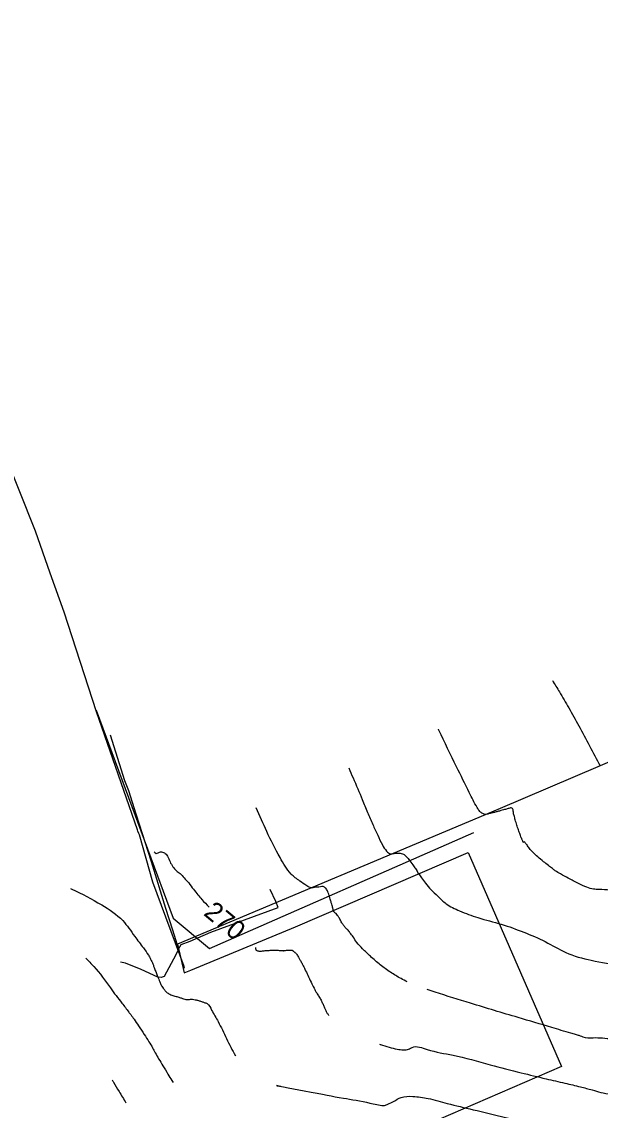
# Model space of a CAD drawing. Extents: x -478645 to -472650, y -1118147 to -1113892.
# Drawn here: x -475798.3 to -475676.6, y -1117014.2 to -1116785 of the extents above; entities that cross this region are included whole.
import ezdxf

# ---------------------------------------------------------------- set-up
doc = ezdxf.new("R2010")
doc.units = 0
for name, color, linetype in [('ObPÚ', 7, 'Continuous'), ('telekomunikační kabel_O2', 7, 'Continuous'), ('VAK_vodovod', 7, 'Continuous'), ('Vrstevnice_hlavni', 7, 'Continuous'), ('Vrstevnice_popis', 7, 'Continuous'), ('Vrstevnice_vedlejsi', 7, 'Continuous')]:
    doc.layers.add(name, color=color, linetype=linetype)

msp = doc.modelspace()

# ---------------------------------------------------------------- linework, layer by layer
at = {"layer": 'ObPÚ'}
msp.add_lwpolyline([(-475428.97, -1116843.96), (-475493.62, -1116794.93), (-475510.01, -1116785), (-475504.39, -1116792.65), (-475500.17, -1116802.88), (-475548.74, -1116836.09), (-475563.15, -1116845.95), (-475582.38, -1116858.98), (-475609.93, -1116877.62), (-475644, -1116900.2), (-475634.09, -1116923.52), (-475698.19, -1116950.87), (-475765.52, -1116979.2), (-475764.15, -1116985.27), (-475762.77, -1116984.68), (-475740.75, -1116975.6), (-475704.37, -1116959.91), (-475684.75, -1117004.96), (-475721.12, -1117020.7)], dxfattribs=at)
at = {"layer": 'telekomunikační kabel_O2'}
for points in [[(-475779.72, -1116935.16), (-475776.72, -1116944.8), (-475775.82, -1116946.89)], [(-475775.82, -1116946.89), (-475774.3, -1116951.81), (-475771.12, -1116961.84), (-475768.06, -1116971.62), (-475766.62, -1116976.22), (-475765.34, -1116980.29)], [(-475765.34, -1116980.29), (-475764.8, -1116979.28), (-475762.86, -1116978.62), (-475758.55, -1116976.73), (-475744.37, -1116971.54), (-475744.83, -1116970.26), (-475746.06, -1116967.73)], [(-475765.34, -1116980.29), (-475765.92, -1116981.46), (-475768.35, -1116986.07), (-475768.98, -1116986.28), (-475769.68, -1116986.19), (-475773.18, -1116984.59), (-475776.5, -1116983.23), (-475777.53, -1116983.05)]]:
    msp.add_lwpolyline(points, dxfattribs=at)
at = {"layer": 'VAK_vodovod'}
for points in [[(-475764.07, -1116984.29), (-475764.159, -1116983.95), (-475770.76, -1116966.2), (-475773.519, -1116956.18), (-475773.699, -1116955.909), (-475773.909, -1116955.44), (-475773.98, -1116955.18), (-475782.599, -1116930.34), (-475789.389, -1116909.29), (-475792.36, -1116901.129), (-475795.449, -1116892.25), (-475795.679, -1116891.569), (-475801.449, -1116877.079), (-475803.873, -1116870.356), (-475810.739, -1116851.899), (-475813.889, -1116838.01), (-475814.349, -1116835.61), (-475816.44, -1116816.799), (-475816.731, -1116810.878)], [(-475782.684, -1116929.977), (-475766.44, -1116973.781), (-475758.82, -1116980.133), (-475703.189, -1116955.74)]]:
    msp.add_lwpolyline(points, dxfattribs=at)
at = {"layer": 'Vrstevnice_hlavni'}
for points in [[(-475770.444, -1116959.812), (-475770.027, -1116960.112), (-475769.102, -1116959.807), (-475768.308, -1116960.004), (-475767.648, -1116960.702), (-475767.119, -1116961.902), (-475766.503, -1116962.916), (-475765.799, -1116963.743), (-475765.007, -1116964.385), (-475764.139, -1116965.254), (-475763.195, -1116966.349), (-475762.174, -1116967.671), (-475761.246, -1116968.823), (-475760.408, -1116969.806), (-475758.917, -1116971.433)], [(-475752.155, -1116974.761), (-475752.278, -1116974.524), (-475752.331, -1116974.447), (-475752.377, -1116974.41), (-475752.415, -1116974.415), (-475752.45, -1116974.42), (-475752.482, -1116974.426), (-475752.541, -1116974.439)], [(-475749.112, -1116979.911), (-475749.084, -1116980.363), (-475748.966, -1116980.529), (-475748.744, -1116980.634), (-475748.419, -1116980.68), (-475748.159, -1116980.701), (-475747.966, -1116980.699), (-475747.84, -1116980.673), (-475747.554, -1116980.64), (-475747.109, -1116980.599), (-475746.506, -1116980.551), (-475746.066, -1116980.515), (-475745.792, -1116980.49), (-475745.682, -1116980.477), (-475745.442, -1116980.476), (-475745.072, -1116980.485), (-475744.572, -1116980.507), (-475744.144, -1116980.533), (-475743.788, -1116980.563), (-475743.504, -1116980.598), (-475743.314, -1116980.614), (-475743.221, -1116980.611), (-475743.223, -1116980.59), (-475743.216, -1116980.574), (-475743.201, -1116980.564), (-475743.178, -1116980.559), (-475742.98, -1116980.549), (-475742.607, -1116980.532), (-475742.059, -1116980.51), (-475741.674, -1116980.502), (-475741.452, -1116980.509), (-475741.392, -1116980.531), (-475741.34, -1116980.559), (-475741.298, -1116980.593), (-475741.264, -1116980.634), (-475741.175, -1116980.708), (-475741.032, -1116980.815), (-475740.833, -1116980.954), (-475740.632, -1116981.157), (-475740.429, -1116981.424), (-475740.222, -1116981.754), (-475739.954, -1116982.217), (-475739.622, -1116982.813), (-475739.228, -1116983.543), (-475738.734, -1116984.524), (-475738.14, -1116985.756), (-475737.446, -1116987.241), (-475736.821, -1116988.49), (-475736.265, -1116989.503), (-475735.779, -1116990.281), (-475735.354, -1116991.032), (-475734.993, -1116991.754), (-475734.695, -1116992.449), (-475734.397, -1116993.087), (-475734.1, -1116993.67), (-475733.804, -1116994.197), (-475733.754, -1116994.287)], [(-475723.019, -1117000.326), (-475722.854, -1117000.379), (-475721.016, -1117000.925), (-475719.348, -1117001.335), (-475717.982, -1117001.478), (-475716.917, -1117001.356), (-475716.153, -1117000.967), (-475713.042, -1117001.384), (-475707.582, -1117002.608), (-475699.774, -1117004.638), (-475693.246, -1117006.296), (-475687.998, -1117007.584), (-475684.03, -1117008.499), (-475680.792, -1117009.282), (-475678.284, -1117009.933), (-475676.506, -1117010.452), (-475672.106, -1117010.892), (-475665.083, -1117011.253)]]:
    msp.add_spline(points, degree=3, dxfattribs=at)
at = {"layer": 'Vrstevnice_vedlejsi'}
for points in [[(-475686.67, -1116923.726), (-475685.202, -1116926.107), (-475683.236, -1116929.464), (-475681.126, -1116933.254), (-475676.619, -1116941.699)], [(-475589.216, -1117124.456), (-475591.425, -1117122.152), (-475592.659, -1117119.687), (-475592.919, -1117117.061), (-475592.203, -1117114.274), (-475589.888, -1117108.69), (-475585.974, -1117100.309), (-475580.459, -1117089.13), (-475576.812, -1117078.878), (-475575.031, -1117069.554), (-475575.117, -1117061.157), (-475574.636, -1117054.237), (-475573.59, -1117048.792), (-475571.977, -1117044.824), (-475570.898, -1117041.096), (-475570.353, -1117037.61), (-475570.342, -1117034.364), (-475569.433, -1117028.448), (-475567.626, -1117019.86), (-475564.922, -1117008.6), (-475567.235, -1116998.791), (-475574.567, -1116990.433), (-475586.916, -1116983.524), (-475597.186, -1116978.942), (-475605.377, -1116976.688), (-475611.489, -1116976.76), (-475618.025, -1116976.271), (-475624.984, -1116975.222), (-475632.368, -1116973.612), (-475641.296, -1116972.066), (-475651.771, -1116970.583), (-475663.792, -1116969.164), (-475672.17, -1116968.202), (-475676.905, -1116967.697), (-475677.998, -1116967.647), (-475679.435, -1116967.24), (-475681.215, -1116966.473), (-475683.339, -1116965.348), (-475684.96, -1116964.449), (-475686.077, -1116963.776), (-475686.69, -1116963.33), (-475687.51, -1116962.691), (-475688.536, -1116961.862), (-475689.768, -1116960.841), (-475690.758, -1116959.916), (-475691.505, -1116959.085), (-475692.008, -1116958.349), (-475692.376, -1116957.889), (-475692.608, -1116957.705), (-475692.704, -1116957.796), (-475692.881, -1116957.567), (-475693.138, -1116957.016), (-475693.475, -1116956.145), (-475693.813, -1116955.193), (-475694.151, -1116954.161), (-475694.489, -1116953.05), (-475694.736, -1116952.145), (-475694.892, -1116951.446), (-475694.956, -1116950.954), (-475695.105, -1116950.65), (-475695.339, -1116950.535), (-475695.658, -1116950.608), (-475696, -1116950.692), (-475696.364, -1116950.788), (-475696.75, -1116950.896), (-475697.237, -1116951.031), (-475697.824, -1116951.194), (-475698.511, -1116951.385), (-475699.213, -1116951.569), (-475699.928, -1116951.744), (-475700.656, -1116951.912), (-475701.333, -1116951.752), (-475701.956, -1116951.263), (-475702.527, -1116950.446), (-475704.154, -1116947.323), (-475706.837, -1116941.893), (-475710.575, -1116934.156), (-475710.663, -1116933.973)], [(-475729.527, -1116942.126), (-475728.611, -1116944.232), (-475726.669, -1116948.766), (-475725.544, -1116951.506), (-475724.466, -1116954.013), (-475723.434, -1116956.285), (-475722.449, -1116958.323), (-475721.548, -1116959.642), (-475720.729, -1116960.242), (-475719.994, -1116960.123), (-475719.328, -1116960.075), (-475718.731, -1116960.097), (-475718.204, -1116960.189), (-475717.583, -1116960.628), (-475716.868, -1116961.415), (-475716.061, -1116962.548), (-475715.508, -1116963.328), (-475715.21, -1116963.755), (-475715.167, -1116963.828), (-475715.132, -1116963.894), (-475715.104, -1116963.952), (-475715.085, -1116964.003), (-475714.792, -1116964.431), (-475714.224, -1116965.237), (-475713.382, -1116966.419), (-475712.234, -1116967.726), (-475710.782, -1116969.156), (-475709.024, -1116970.711), (-475706.212, -1116972.209), (-475702.344, -1116973.649), (-475697.421, -1116975.031), (-475692.698, -1116976.716), (-475688.176, -1116978.703), (-475683.853, -1116980.992), (-475678.496, -1116982.63), (-475672.102, -1116983.615), (-475664.674, -1116983.949), (-475657.807, -1116984.398), (-475651.502, -1116984.961), (-475645.759, -1116985.639), (-475640.754, -1116986.347), (-475636.487, -1116987.086), (-475632.96, -1116987.855), (-475627.187, -1116988.328), (-475619.17, -1116988.503), (-475608.909, -1116988.382), (-475599.585, -1116989.691), (-475591.198, -1116992.428), (-475583.75, -1116996.595), (-475579.328, -1117001.637), (-475577.932, -1117007.554), (-475579.563, -1117014.345), (-475580.658, -1117021.082), (-475581.217, -1117027.766), (-475581.24, -1117034.395), (-475582.353, -1117041.517), (-475584.557, -1117049.132), (-475587.852, -1117057.238), (-475590.037, -1117063.798), (-475591.112, -1117068.811)], [(-475717.205, -1116987.161), (-475718.526, -1116986.479), (-475720.741, -1116985.146), (-475722.885, -1116983.579), (-475724.958, -1116981.78), (-475726.601, -1116980.203), (-475727.814, -1116978.85), (-475728.597, -1116977.719), (-475729.263, -1116976.822), (-475729.811, -1116976.161), (-475730.242, -1116975.734), (-475730.666, -1116975.194), (-475731.082, -1116974.541), (-475731.491, -1116973.775), (-475731.855, -1116973.196), (-475732.174, -1116972.806), (-475732.448, -1116972.604), (-475732.637, -1116972.443), (-475732.741, -1116972.325), (-475732.761, -1116972.248), (-475732.78, -1116972.148), (-475732.799, -1116972.022), (-475732.818, -1116971.873), (-475732.873, -1116971.625), (-475732.966, -1116971.279), (-475733.095, -1116970.835), (-475733.299, -1116970.169), (-475733.575, -1116969.283), (-475733.925, -1116968.175), (-475734.359, -1116967.454), (-475734.877, -1116967.121), (-475735.478, -1116967.174), (-475736.089, -1116967.235), (-475736.708, -1116967.302), (-475737.336, -1116967.376), (-475738.368, -1116966.928), (-475739.805, -1116965.959), (-475741.646, -1116964.467), (-475743.969, -1116960.984), (-475746.775, -1116955.511), (-475748.963, -1116950.527)], [(-475788.03, -1116967.518), (-475787.795, -1116967.629), (-475781.498, -1116970.952), (-475777.078, -1116974.275), (-475774.537, -1116977.597), (-475772.727, -1116980.026), (-475771.647, -1116981.561), (-475771.297, -1116982.202), (-475770.979, -1116982.851), (-475770.692, -1116983.509), (-475770.437, -1116984.176), (-475770.136, -1116984.956), (-475769.79, -1116985.85), (-475769.398, -1116986.858), (-475769.136, -1116987.532), (-475769.004, -1116987.871), (-475769.002, -1116987.876), (-475769.001, -1116987.879), (-475769, -1116987.882), (-475768.999, -1116987.883), (-475768.999, -1116987.884), (-475768.998, -1116987.885), (-475768.852, -1116988.086), (-475768.561, -1116988.488), (-475768.125, -1116989.09), (-475767.529, -1116989.58), (-475766.772, -1116989.959), (-475765.856, -1116990.227), (-475765.092, -1116990.457), (-475764.483, -1116990.649), (-475764.027, -1116990.804), (-475763.601, -1116990.885), (-475763.205, -1116990.894), (-475762.84, -1116990.829), (-475762.377, -1116990.842), (-475761.816, -1116990.934), (-475761.157, -1116991.103), (-475760.523, -1116991.296), (-475759.914, -1116991.513), (-475759.331, -1116991.753), (-475758.359, -1116993.097), (-475756.997, -1116995.545), (-475755.247, -1116999.097), (-475753.369, -1117002.735)], [(-475784.856, -1116982.194), (-475783.127, -1116983.939), (-475779.673, -1116988.456), (-475777.228, -1116991.651), (-475775.793, -1116993.524), (-475775.368, -1116994.076), (-475774.686, -1116995.045), (-475773.746, -1116996.433), (-475772.548, -1116998.239), (-475771.564, -1116999.784), (-475770.793, -1117001.068), (-475770.234, -1117002.092), (-475769.508, -1117003.352), (-475768.615, -1117004.851), (-475767.555, -1117006.586), (-475766.714, -1117007.974), (-475766.472, -1117008.379)], [(-475648.003, -1117000.173), (-475655.316, -1116999.958), (-475662.118, -1116999.729), (-475668.41, -1116999.485), (-475674.19, -1116999.225), (-475678.133, -1116999.004), (-475680.239, -1116998.823), (-475680.506, -1116998.681), (-475681.023, -1116998.492), (-475681.789, -1116998.255), (-475682.805, -1116997.969), (-475686.83, -1116996.779), (-475693.865, -1116994.683), (-475703.91, -1116991.682), (-475711.368, -1116989.315), (-475712.997, -1116988.771)], [(-475779.319, -1117007.791), (-475779.013, -1117008.308), (-475777.842, -1117010.255), (-475776.381, -1117012.646)], [(-475743.816, -1117009.188), (-475744.435, -1117009.073), (-475738.882, -1117010.109), (-475730.644, -1117011.656), (-475725.08, -1117012.685), (-475722.191, -1117013.195), (-475721.975, -1117013.186), (-475721.285, -1117012.901), (-475720.12, -1117012.341), (-475718.481, -1117011.506), (-475716.047, -1117011.297), (-475712.82, -1117011.716), (-475708.798, -1117012.762), (-475703.378, -1117014.091), (-475696.56, -1117015.703), (-475688.344, -1117017.599), (-475681.639, -1117019.22), (-475676.446, -1117020.568), (-475672.765, -1117021.642), (-475668.29, -1117022.417), (-475663.022, -1117022.893), (-475656.96, -1117023.071), (-475651.811, -1117023.298), (-475647.576, -1117023.576), (-475644.255, -1117023.903), (-475641.565, -1117024.203), (-475639.507, -1117024.475)]]:
    msp.add_spline(points, degree=3, dxfattribs=at)

# ---------------------------------------------------------------- texts
at = {"layer": 'Vrstevnice_popis'}
msp.add_text(' 270 ', height=4, rotation=320.18645, dxfattribs=at).set_placement((-475761.384, -1116972.015))

doc.saveas('drawing.dxf')
